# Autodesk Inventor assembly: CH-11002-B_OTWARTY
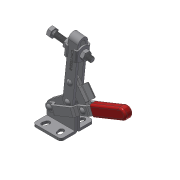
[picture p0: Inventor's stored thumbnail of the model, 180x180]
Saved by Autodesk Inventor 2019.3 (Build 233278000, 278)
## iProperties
Company: Î¢ÈíÖÐ¹ú
Created: 2012-09
Part Number: CH-11002-B_OTWARTY
Material: Ogólny
Description: STEP AP203
Document SubType Name: Assembly
Designer: CADENGINEERING4
Sending System: SolidWorks 2010
Preprocessor: SwSTEP 2.0
Title: CH-11002-B.STEP
Author: Î¢ÈíÓÃ»§
Revision Number: ÈÎºÎ
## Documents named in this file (9)
- D:\Vault_2016\Projekty\NASZ KATALOG\CLAMPTEK\STRONA\Vertical toggle clamp\CH-11002-B\CH-11002-B_OTWARTY.iam
- D:\Vault_2016\Projekty\NASZ KATALOG\CLAMPTEK\STEP FILES\Vertical toggle clamp\CH-11002-B\CH-FW-140.ipt
- D:\Vault_2016\Projekty\NASZ KATALOG\CLAMPTEK\STEP FILES\Vertical toggle clamp\CH-11002-B\CH-11002-B-06.ipt
- D:\Vault_2016\Projekty\NASZ KATALOG\CLAMPTEK\STEP FILES\Vertical toggle clamp\CH-11002-B\CH-11002-B-02 U-BAR.ipt
- D:\Vault_2016\Projekty\NASZ KATALOG\CLAMPTEK\STEP FILES\Vertical toggle clamp\CH-11002-B\CH-11002-B-01 FLABGED BASE.ipt
- D:\Vault_2016\Projekty\NASZ KATALOG\CLAMPTEK\STEP FILES\Vertical toggle clamp\CH-11002-B\M5 NUT.ipt
- D:\Vault_2016\Projekty\NASZ KATALOG\CLAMPTEK\STEP FILES\Vertical toggle clamp\CH-11002-B\CH-11002-B-04 CONNECTING-PLATE.ipt
- D:\Vault_2016\Projekty\NASZ KATALOG\CLAMPTEK\STEP FILES\Vertical toggle clamp\CH-11002-B\M5X40.ipt
- D:\Vault_2016\Projekty\NASZ KATALOG\CLAMPTEK\STEP FILES\Vertical toggle clamp\CH-11002-B\CH-11002-B-03 HANDLE.ipt
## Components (13 placed, 8 different names)
1. CH-11002-B-01 FLABGED BASE_6
2. CH-FW-140:3 — Zestawiające:2, Zestawiające:6, Zestawiające:8, Równoległe:1
3. CH-FW-140:4 — Zestawiające:4, Zestawiające:5, Zestawiające:7, Równoległe:1, Kątowe:1
4. CH-11002-B-06:5 — Zestawiające:14, Zestawiające:15, Zestawiające:16
5. CH-11002-B-02 U-BAR:2 — Zestawiające:5, Zestawiające:6, Zestawiające:14, Zestawiające:15, Zestawiające:16, Zestawiające:17, Zestawiające:18, Zestawiające:19, Zestawiające:21, Zestawiające:22, Zestawiające:23, Kątowe:1, Równoległe:2, Zestawiające:26
6. CH-11002-B-06:6 — Zestawiające:11, Zestawiające:12
7. CH-11002-B-06:7 — Zestawiające:17, Zestawiające:18, Zestawiające:19, Zestawiające:20
8. M5 NUT:3 — Zestawiające:1, Zestawiające:8
9. M5 NUT:4 — Zestawiające:3, Zestawiające:7, Zestawiające:23
10. CH-11002-B-04 CONNECTING-PLATE:2 — Zestawiające:10, Zestawiające:20, Zestawiające:26, Zestawiające:27
11. M5X40:2 — Zestawiające:1, Zestawiające:2, Zestawiające:3, Zestawiające:4, Zestawiające:21, Zestawiające:22, Równoległe:2
12. CH-11002-B-06:8 — Zestawiające:9, Zestawiające:10, Zestawiające:13
13. CH-11002-B-03 HANDLE:2 — Zestawiające:9, Zestawiające:11, Zestawiające:12, Zestawiające:13, Zestawiające:27
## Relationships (28: Mate 25, Flush 2, Angle 1)
- Zestawiające:1 [Mate]: M5 NUT:3 ↔ M5X40:2
- Zestawiające:2 [Mate]: CH-FW-140:3 ↔ M5X40:2
- Zestawiające:3 [Mate]: M5 NUT:4 ↔ M5X40:2
- Zestawiające:4 [Mate]: CH-FW-140:4 ↔ M5X40:2
- Zestawiające:5 [Mate]: CH-FW-140:4 ↔ CH-11002-B-02 U-BAR:2
- Zestawiające:6 [Mate]: CH-FW-140:3 ↔ CH-11002-B-02 U-BAR:2
- Zestawiające:7 [Mate]: CH-FW-140:4 ↔ M5 NUT:4
- Zestawiające:8 [Mate]: CH-FW-140:3 ↔ M5 NUT:3
- Zestawiające:9 [Mate]: CH-11002-B-06:8 ↔ CH-11002-B-03 HANDLE:2
- Zestawiające:10 [Mate]: CH-11002-B-04 CONNECTING-PLATE:2 ↔ CH-11002-B-06:8
- Zestawiające:11 [Mate]: CH-11002-B-06:6 ↔ CH-11002-B-03 HANDLE:2
- Zestawiające:12 [Mate]: CH-11002-B-06:6 ↔ CH-11002-B-03 HANDLE:2
- Zestawiające:13 [Mate]: CH-11002-B-06:8 ↔ CH-11002-B-03 HANDLE:2
- Zestawiające:14 [Mate]: CH-11002-B-06:5 ↔ CH-11002-B-02 U-BAR:2
- Zestawiające:15 [Mate]: CH-11002-B-06:5 ↔ CH-11002-B-02 U-BAR:2
- Zestawiające:16 [Mate]: CH-11002-B-06:5 ↔ CH-11002-B-02 U-BAR:2
- Zestawiające:17 [Mate]: CH-11002-B-02 U-BAR:2 ↔ CH-11002-B-06:7
- Zestawiające:18 [Mate]: CH-11002-B-02 U-BAR:2 ↔ CH-11002-B-06:7
- Zestawiające:19 [Mate]: CH-11002-B-02 U-BAR:2 ↔ CH-11002-B-06:7
- Zestawiające:20 [Mate]: CH-11002-B-06:7 ↔ CH-11002-B-04 CONNECTING-PLATE:2
- Zestawiające:21 [Mate]: CH-11002-B-02 U-BAR:2 ↔ M5X40:2
- Zestawiające:22 [Mate]: CH-11002-B-02 U-BAR:2 ↔ M5X40:2
- Zestawiające:23 [Mate]: CH-11002-B-02 U-BAR:2 ↔ M5 NUT:4
- Równoległe:1 [Flush]: CH-FW-140:3 ↔ CH-FW-140:4
- Kątowe:1 [Angle]: CH-FW-140:4 ↔ CH-11002-B-02 U-BAR:2
- Równoległe:2 [Flush]: CH-11002-B-02 U-BAR:2 ↔ M5X40:2
- Zestawiające:26 [Mate]: CH-11002-B-02 U-BAR:2 ↔ CH-11002-B-04 CONNECTING-PLATE:2
- Zestawiające:27 [Mate]: CH-11002-B-04 CONNECTING-PLATE:2 ↔ CH-11002-B-03 HANDLE:2
